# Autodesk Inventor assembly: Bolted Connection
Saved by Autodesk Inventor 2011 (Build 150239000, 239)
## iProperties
Created: 2020-12
Part Number: Bolted Connection
Document SubType Name: Assembly
Designer: PC
ClientObjectVersion: 1
Author: PC
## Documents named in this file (3)
- C:\Users\PC\Documents\Inventor\workshop-crane-powered-by-drill\estructura-principal\Design Accelerator\Bolted Connection7.iam
- C:\Users\PC\Documents\Inventor\Content Center Files\R2011\en-US\DIN 931-1\DIN 931-1 - M14 x 75.ipt
- C:\Users\PC\Documents\Inventor\Content Center Files\R2011\en-US\DIN 555\DIN 555-5 - M14.ipt
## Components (2 placed, 2 different names)
1. DIN 931-1 - replaced by DIN EN 24014 M14 x 75:1
2. DIN 555 - replaced by DIN EN 24034 M14:1
